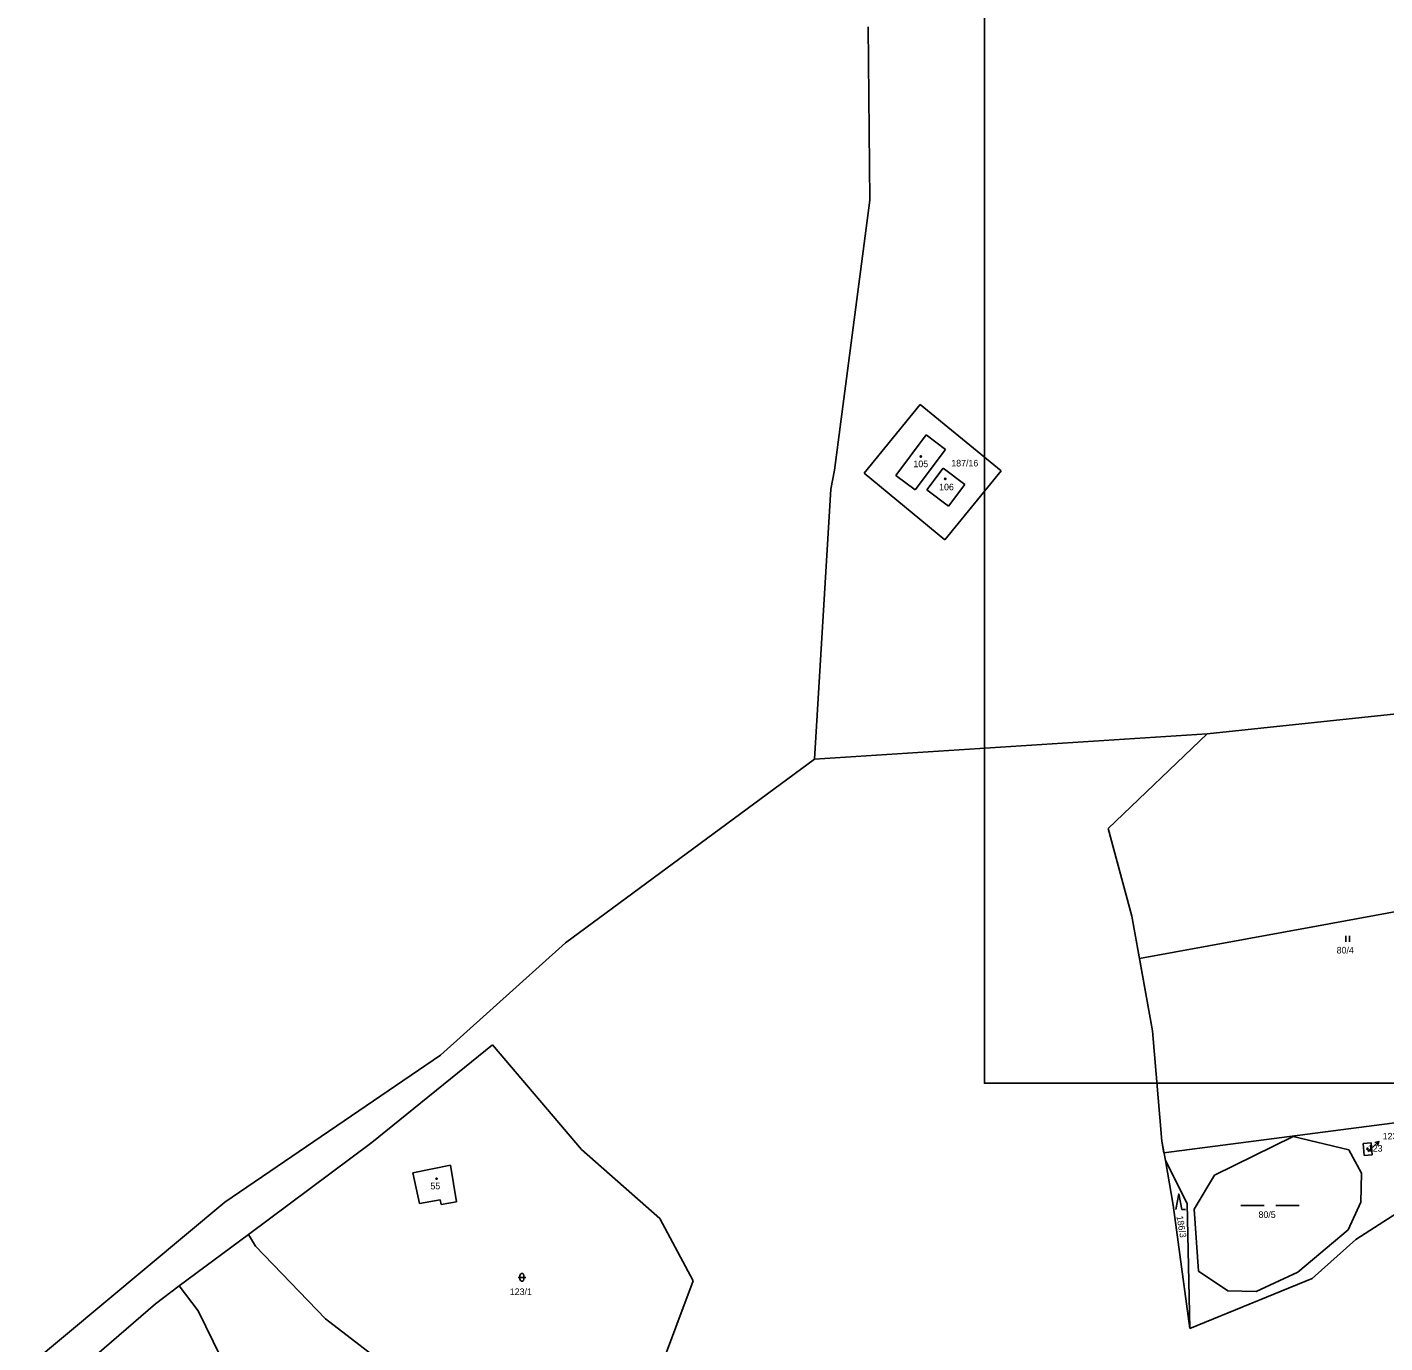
# Model space of a CAD drawing. Extents: x -811039 to -805820, y -1161436 to -1155864.
# Drawn here: x -807121.9 to -806771.7, y -1158066.9 to -1157727.6 of the extents above; entities that cross this region are included whole.
import ezdxf

# ---------------------------------------------------------------- set-up
doc = ezdxf.new("R2010")
doc.units = 0
for name, color, linetype in [('Default', 7, 'Continuous'), ('Hranice kat_území', 7, 'Continuous'), ('Hranice parcel', 7, 'Continuous'), ('ML1000', 7, 'Continuous'), ('Parcelní čísla', 7, 'Continuous'), ('Pop  PČ popisy', 7, 'Continuous'), ('Věcná břemena k části', 7, 'Continuous'), ('Značky budov', 7, 'Continuous'), ('Značky kultur', 7, 'Continuous')]:
    doc.layers.add(name, color=color, linetype=linetype)

# ---------------------------------------------------------------- blocks, each defined once
blk = doc.blocks.new('306')
at = {"layer": 'Default'}
for p, q in [((-0.5, 1.5), (-0.5, 0)), ((0.5, 0), (0.5, 1.5))]:
    blk.add_line(p, q, dxfattribs=at)
blk = doc.blocks.new('308')
at = {"layer": 'Default'}
blk.add_lwpolyline([(-0.75, 0), (0, 4), (0.75, 0), (1.75, 0)], dxfattribs=at)
blk = doc.blocks.new('316')
at = {"layer": 'Default'}
for points in [[(-1, 1), (0.27, 1), (1, 1)], [(-0.5, 1.5), (-0.4, 1.79), (-0.15, 1.97), (0.16, 1.97), (0.41, 1.79), (0.51, 1.5), (0.51, 0.5), (0.41, 0.21), (0.16, 0.03), (-0.15, 0.03), (-0.4, 0.21), (-0.5, 0.5), (-0.5, 1.5)]]:
    blk.add_lwpolyline(points, dxfattribs=at)
blk = doc.blocks.new('803')
at = {"layer": 'Default'}
for p, q in [((-7.5, 0), (-1.5, 0)), ((1.5, 0), (7.5, 0))]:
    blk.add_line(p, q, dxfattribs=at)
blk = doc.blocks.new('10292')
at = {"layer": 'Default'}
blk.add_line((0, 3), (0, 0), dxfattribs=at)
blk.add_lwpolyline([(-0.5, 2), (0, 3), (0.5, 2)], dxfattribs=at)
blk = doc.blocks.new('402')
at = {"layer": 'Default'}
blk.add_lwpolyline([(0.09, 0.15), (0.18, 0), (0.09, -0.15), (-0.09, -0.15), (-0.18, 0), (-0.09, 0.15), (0.09, 0.15)], dxfattribs=at)

msp = doc.modelspace()

# ---------------------------------------------------------------- linework, layer by layer
at = {"layer": 'Hranice kat_území'}
for p, q in [((-806904.94, -1157727.56), (-806904.51, -1157772.27)), ((-806904.94, -1157727.56), (-806904.51, -1157772.27)), ((-806904.51, -1157772.27), (-806913.67, -1157841.92)), ((-806904.51, -1157772.27), (-806913.67, -1157841.92)), ((-806914.59, -1157846.83), (-806913.67, -1157841.92)), ((-806914.59, -1157846.83), (-806913.67, -1157841.92)), ((-806918.82, -1157916.41), (-806914.59, -1157846.83)), ((-806918.82, -1157916.41), (-806914.59, -1157846.83)), ((-806918.82, -1157916.41), (-806983.04, -1157963.76)), ((-806918.82, -1157916.41), (-806983.04, -1157963.76)), ((-806983.04, -1157963.76), (-807015.26, -1157992.79)), ((-806983.04, -1157963.76), (-807015.26, -1157992.79)), ((-807015.26, -1157992.79), (-807070.96, -1158030.65)), ((-807015.26, -1157992.79), (-807070.96, -1158030.65)), ((-807070.96, -1158030.65), (-807121.92, -1158073.2)), ((-807070.96, -1158030.65), (-807121.92, -1158073.2))]:
    msp.add_line(p, q, dxfattribs=at)
at = {"layer": 'Hranice parcel'}
for p, q in [((-806906.04, -1157842.65), (-806891.54, -1157824.95)), ((-806891.54, -1157824.95), (-806870.67, -1157842.05)), ((-806897.86, -1157843.25), (-806890, -1157832.76)), ((-806890, -1157832.76), (-806884.99, -1157836.53)), ((-806884.99, -1157836.53), (-806892.84, -1157847)), ((-806889.8, -1157847), (-806885.58, -1157841.39)), ((-806885.58, -1157841.39), (-806879.99, -1157845.59)), ((-806885.18, -1157859.86), (-806906.04, -1157842.65)), ((-806892.84, -1157847), (-806897.86, -1157843.25)), ((-806870.67, -1157842.05), (-806885.18, -1157859.86)), ((-806884.21, -1157851.19), (-806889.8, -1157847)), ((-806879.99, -1157845.59), (-806884.21, -1157851.19)), ((-806817.49, -1157909.9), (-806760.28, -1157903.83)), ((-806817.49, -1157909.9), (-806918.82, -1157916.41)), ((-806843.07, -1157934.32), (-806817.49, -1157909.9)), ((-806836.94, -1157956.88), (-806843.07, -1157934.32)), ((-806831.65, -1157986.44), (-806836.94, -1157956.88)), ((-806831.65, -1157986.44), (-806829.24, -1158014.95)), ((-807001.87, -1157990.06), (-807032.99, -1158015.3)), ((-806978.9, -1158017.04), (-807001.87, -1157990.06)), ((-807064.85, -1158038.99), (-807032.99, -1158015.3)), ((-806829.24, -1158014.95), (-806828.28, -1158019.94)), ((-806815.6, -1158023.66), (-806795.32, -1158013.71)), ((-806795.32, -1158013.71), (-806780.95, -1158017.13)), ((-806775.18, -1158015.36), (-806777.27, -1158015.52)), ((-806777.27, -1158015.52), (-806777.06, -1158018.61)), ((-806774.99, -1158018.42), (-806775.18, -1158015.36)), ((-806958.71, -1158034.89), (-806978.9, -1158017.04)), ((-806828.28, -1158019.94), (-806826.26, -1158031.41)), ((-806828.28, -1158019.94), (-806822.69, -1158031.03)), ((-806780.95, -1158017.13), (-806777.75, -1158023.16)), ((-806777.06, -1158018.61), (-806774.99, -1158018.42)), ((-807012.73, -1158021.11), (-807022.4, -1158023.12)), ((-807020.75, -1158031), (-807022.4, -1158023.12)), ((-807011.14, -1158030.6), (-807012.73, -1158021.11)), ((-806820.89, -1158032.46), (-806815.6, -1158023.66)), ((-806777.75, -1158023.16), (-806777.87, -1158030.68)), ((-806756.36, -1158025.64), (-806779.2, -1158040.26)), ((-807020.75, -1158031), (-807015.38, -1158030.02)), ((-807015.38, -1158030.02), (-807015.1, -1158031.23)), ((-807015.1, -1158031.23), (-807011.14, -1158030.6)), ((-806777.87, -1158030.68), (-806781.15, -1158037.79)), ((-806826.26, -1158031.41), (-806822.02, -1158063.21)), ((-806822.69, -1158031.03), (-806822.02, -1158063.21)), ((-806819.72, -1158048.5), (-806820.89, -1158032.46)), ((-806950.1, -1158050.97), (-806958.71, -1158034.89)), ((-806781.15, -1158037.79), (-806794.11, -1158048.73)), ((-807082.72, -1158052.28), (-807064.85, -1158038.99)), ((-807063.01, -1158041.98), (-807064.85, -1158038.99)), ((-806790.45, -1158050.34), (-806779.2, -1158040.26)), ((-807044.99, -1158060.79), (-807063.01, -1158041.98)), ((-806812.15, -1158053.5), (-806819.72, -1158048.5)), ((-806960.13, -1158077.6), (-806950.1, -1158050.97)), ((-806822.02, -1158063.21), (-806790.45, -1158050.34)), ((-806794.11, -1158048.73), (-806804.86, -1158053.74)), ((-807082.72, -1158052.28), (-807088.85, -1158056.84)), ((-807077.81, -1158058.66), (-807082.72, -1158052.28)), ((-806804.86, -1158053.74), (-806812.15, -1158053.5)), ((-807111.46, -1158076.42), (-807088.85, -1158056.84)), ((-807071.97, -1158070.67), (-807077.81, -1158058.66)), ((-807022.58, -1158077.9), (-807044.99, -1158060.79))]:
    msp.add_line(p, q, dxfattribs=at)
at = {"layer": 'ML1000'}
msp.add_lwpolyline([(-806875, -1157000), (-806875, -1158000), (-806250, -1158000), (-806250, -1157000)], close=True, dxfattribs=at)
at = {"layer": 'Pop  PČ popisy'}
msp.add_line((-806776.09, -1158017.63), (-806775.42, -1158017.02), dxfattribs=at)
at = {"layer": 'Věcná břemena k části'}
msp.add_lwpolyline([(-806834.98, -1157967.84), (-806789.3, -1157959.45), (-806742.1, -1157950.78), (-806718.6, -1157948.56), (-806718.2, -1157948.52), (-806631.31, -1157940.29), (-806630.87, -1157947.76), (-806652.6, -1157995.12), (-806709.01, -1158002.43), (-806715.58, -1158003.28), (-806828.66, -1158017.95), (-806829.24, -1158014.95), (-806831.65, -1157986.44)], close=True, dxfattribs=at)
msp.add_lwpolyline([(-806834.98, -1157967.84), (-806789.3, -1157959.45), (-806742.1, -1157950.78), (-806718.6, -1157948.56), (-806718.2, -1157948.52), (-806631.31, -1157940.29), (-806630.87, -1157947.76), (-806652.6, -1157995.12), (-806709.01, -1158002.43), (-806715.58, -1158003.28), (-806828.66, -1158017.95), (-806829.24, -1158014.95), (-806831.65, -1157986.44)], close=True, dxfattribs=at)

# ---------------------------------------------------------------- block references
at = {"layer": 'Pop  PČ popisy', "rotation": -47.73800199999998}
msp.add_blockref('10292', (-806775.42, -1158017.02), dxfattribs=at)
at = {"layer": 'Značky budov'}
for p in [(-806891.41, -1157838.36), (-806885.08, -1157844.14), (-806776.19, -1158016.89), (-807016.31, -1158024.6)]:
    msp.add_blockref('402', p, dxfattribs=at)
at = {"layer": 'Značky kultur'}
for name, p in [('306', (-806781.28, -1157963.52)), ('308', (-806824.84, -1158032.53)), ('803', (-806801.3, -1158031.51)), ('316', (-806994.29, -1158051.05))]:
    msp.add_blockref(name, p, dxfattribs=at)

# ---------------------------------------------------------------- texts
at = {"layer": 'Parcelní čísla'}
for s, p in [('105', (-806893.29, -1157841.12)), ('187/16', (-806883.52, -1157840.93)), ('106', (-806886.66, -1157847.09)), ('80/4', (-806784.11, -1157966.53)), ('123', (-806772.25, -1158014.5)), ('123', (-806776.07, -1158017.63)), ('55', (-807017.89, -1158027.35)), ('80/5', (-806804.27, -1158034.73)), ('123/1', (-806997.41, -1158054.62))]:
    msp.add_text(s, height=1.7, dxfattribs=at).set_placement(p)
msp.add_text('186/3', height=1.7, rotation=279.661, dxfattribs=at).set_placement((-806825.46, -1158034.31))

doc.saveas('drawing.dxf')
